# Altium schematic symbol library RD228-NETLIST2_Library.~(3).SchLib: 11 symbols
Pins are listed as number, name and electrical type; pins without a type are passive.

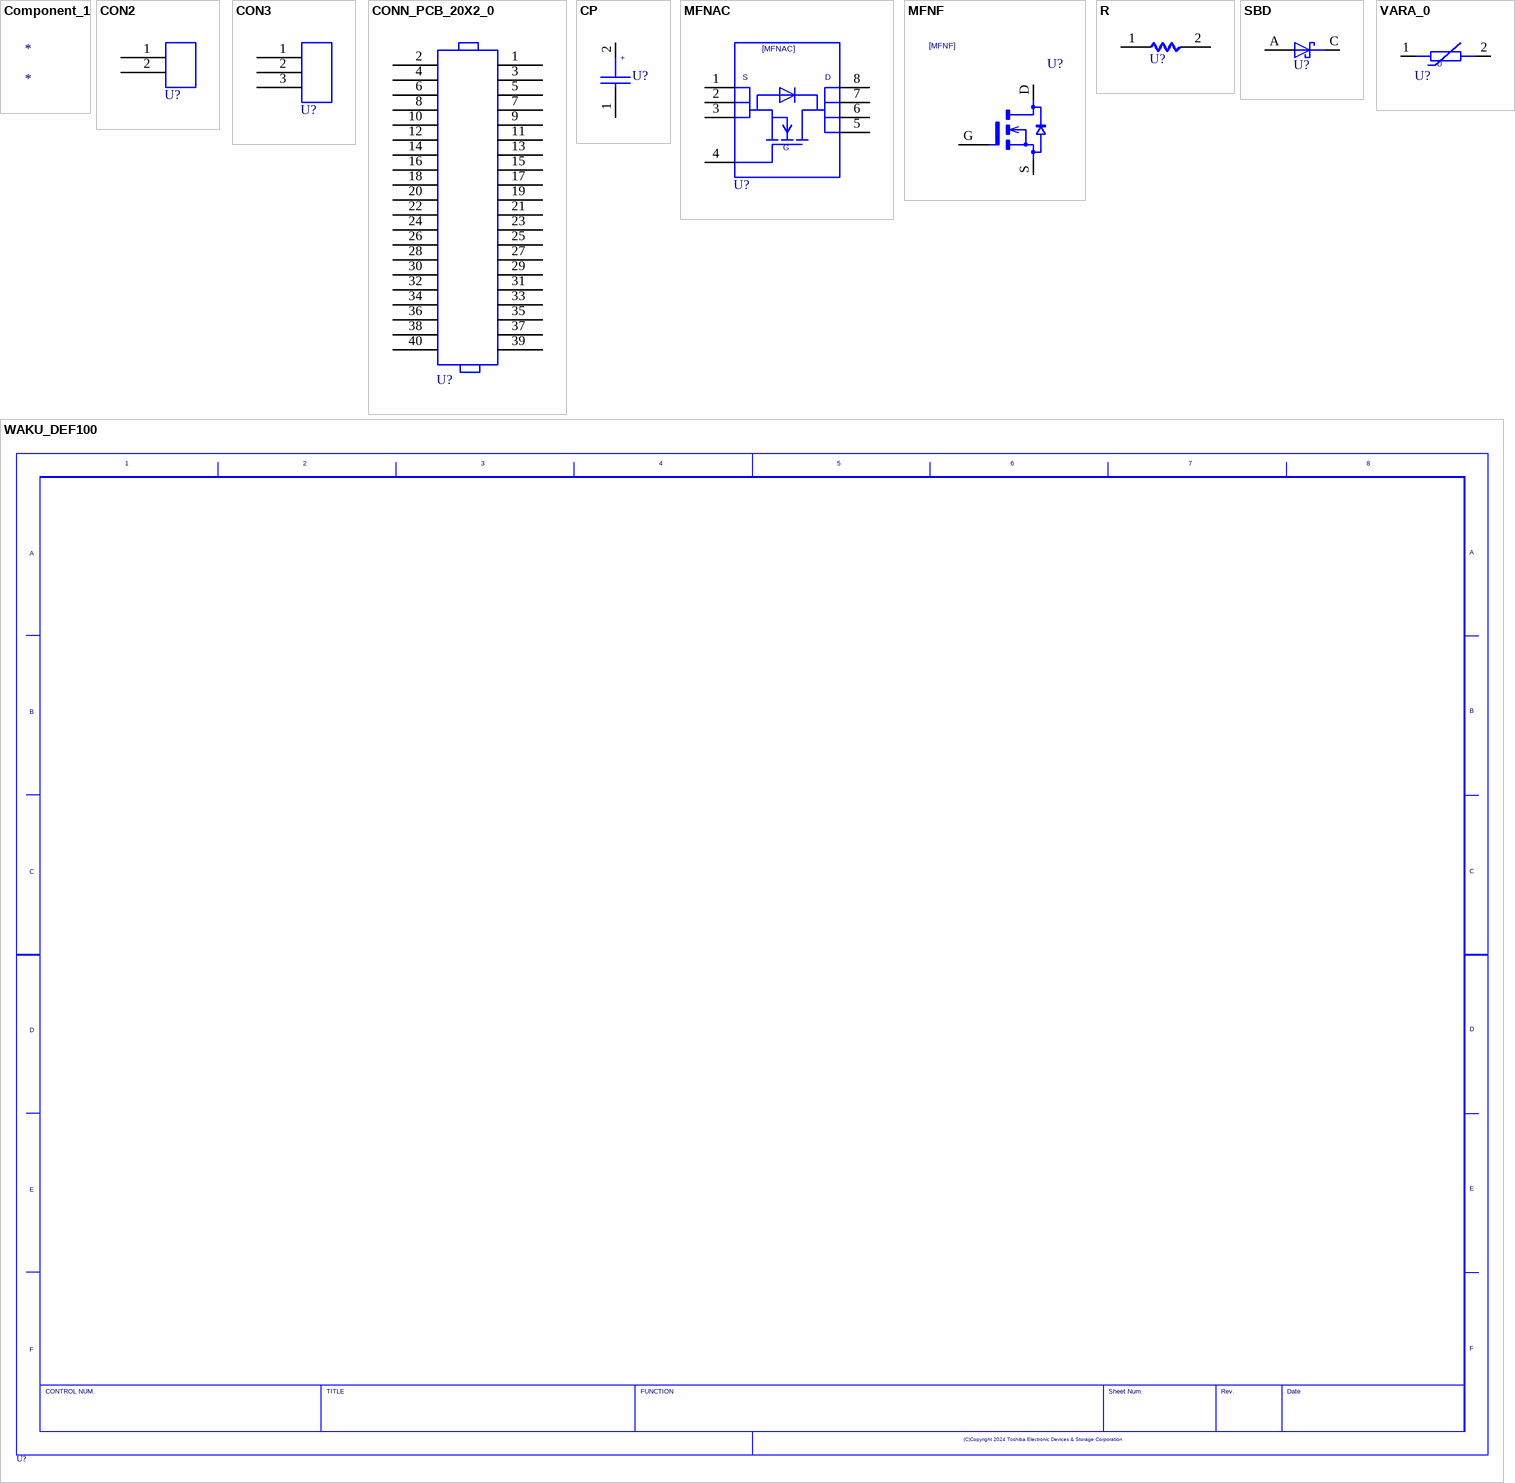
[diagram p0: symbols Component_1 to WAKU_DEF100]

## Component_1
designator *

## CON2
designator U?  (value not drawn)
TIME: 13:16:52; UPDATEUSER: t5459927; SAVECOUNT: 2; __TIME_0__: 1708057012; __FILE_0__: C:/Users/t5459927/Desktop/test_ORCtoSD/RD228-SCHEMATIC2-01/CONNECTOR/CON2.smb; __HOST_0__: t5459927-02; __$Database_ID__: Z-c5718943-9b6a-4755-a070-3d61e98e6b47; OriginalSymbolOrigin: (0,0); Altium-Right: 20; Altium-Bottom: 30
pins: 1, 2

## CON3
designator U?  (value not drawn)
TIME: 13:16:52; UPDATEUSER: t5459927; SAVECOUNT: 2; __TIME_0__: 1708057012; __FILE_0__: C:/Users/t5459927/Desktop/test_ORCtoSD/RD228-SCHEMATIC2-01/CONNECTOR/CON3.smb; __HOST_0__: t5459927-02; __$Database_ID__: Z-e328b140-1b63-4e28-8335-8379fb4ab7a1; OriginalSymbolOrigin: (0,0); Altium-Right: 20; Altium-Bottom: 40
pins: 1, 2, 3

## CONN_PCB_20X2_0
designator U?, comment CONN_PCB_20x2_0  (value not drawn)
TIME: 13:16:52; UPDATEUSER: t5459927; UPDATETIME: 14:51:45; SAVECOUNT: 3; OriginalSymbolOrigin: (0,0); Altium-Right: 40; Altium-Bottom: 230
pins: 1, 2, 3, 4, 5, 6, 7, 8, 9, 10, 11, 12, 13, 14, 15, 16, 17, 18, 19, 20, 21, 22, 23, 24, 25, 26, 27, 28, 29, 30, 31, 32, 33, 34, 35, 36, 37, 38, 39, 40

## CP
designator U?  (value not drawn)
TIME: 15:02:55; UPDATEUSER: fukuda-y; UPDATETIME: 16:13:42; SAVECOUNT: 52; SAVEAREA0: -1450,-153,20294,13055; ORIGINALSYMBOLORIGIN: (0,0); __TIME_0__: 1708057012; __USER_0__: t5459927; __FILE_0__: C:/Users/t5459927/Desktop/test_ORCtoSD/RD228-SCHEMATIC2-01/SMB006/CP.smb; __HOST_0__: t5459927-02; __$Database_ID__: Z-b3d26258-3a88-4599-b1c4-1147a8743763; Altium-Right: 20
pins: 1, 2

## MFNAC
designator U?  (value not drawn)
TIME: 18:29:30; UPDATEUSER: 19990028; UPDATETIME: 14:45:16; SAVECOUNT: 26; SAVEAREA0: -10143,-336,37609,28718; ORIGINALSYMBOLORIGIN: (0,0); __TIME_0__: 1708057012; __USER_0__: t5459927; __FILE_0__: C:/Users/t5459927/Desktop/test_ORCtoSD/RD228-SCHEMATIC2-01/SMB005/MFNAC.smb; __HOST_0__: t5459927-02; __$Database_ID__: Z-b863f03c-2bf8-4525-9966-7b6b866df037; Altium-Right: 70; Altium-Bottom: 90
pins: 1, 2, 3, 4, 5, 6, 7, 8

## MFNF
designator U?  (value not drawn)
TIME: 13:16:52; UPDATEUSER: t5459927; SAVECOUNT: 11; SAVEAREA0: -7027,-292,21786,15988; ORIGINALSYMBOLORIGIN: (0,0); __TIME_0__: 1708057012; __FILE_0__: C:/Users/t5459927/Desktop/test_ORCtoSD/RD228-SCHEMATIC2-01/SMB005/MFNF.smb; __HOST_0__: t5459927-02; __$Database_ID__: Z-a01eb178-07fb-446e-81a1-5aa5c84bcce8; Altium-Right: 40
pins: D, G, S

## R
designator U?  (value not drawn)
TIME: 13:16:51; UPDATEUSER: t5459927; SAVECOUNT: 2; ORIGINALSYMBOLORIGIN: (0,0); __TIME_0__: 1708057011; __FILE_0__: C:/Users/t5459927/Desktop/test_ORCtoSD/RD228-SCHEMATIC2-01/SMB007/R.smb; __HOST_0__: t5459927-02; __$Database_ID__: Z-1d8715ec-4297-42d6-bed7-916b1ffe081f; Altium-Right: 20
pins: 1, 2

## SBD
designator U?  (value not drawn)
SAVEAREA0: -4630,-153,17114,13055; TIME: 14:49:55; UPDATEUSER: fukuda-y; UPDATETIME: 08:16:22; SAVECOUNT: 9; OriginalSymbolOrigin: (5080,5080); Altium-Right: 20
pins: A, C

## VARA_0
designator U?, comment VARA  (value not drawn)
TIME: 09:56:50; UPDATEUSER: tomizawa-y; SAVECOUNT: 12; COMP: VARA_0; SAVEAREA0: -9950,-8554,25168,13619; ORIGINALSYMBOLORIGIN: (0,0); __TIME_0__: 1708057012; __USER_0__: t5459927; __FILE_0__: C:/Users/t5459927/Desktop/test_ORCtoSD/RD228-SCHEMATIC2-01/RD228_SMCD_RM______/VARA_0.smb; __HOST_0__: t5459927-02; __$Database_ID__: Z-830099c9-1790-46fb-9e01-bc8e5a804c28; Altium-Right: 40; Altium-Bottom: 20
pins: 1, 2

## WAKU_DEF100
designator U?  (value not drawn)
TIME: 14:30:25; UPDATEUSER: cae; UPDATETIME: 18:29:18; SAVECOUNT: 3; PLOTTIME: HH:MM; SAVEAREA0: -63393,-16950,474261,314592; ORIGINALSYMBOLORIGIN: (0,0); Altium-Right: 1570; Altium-Bottom: 1070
